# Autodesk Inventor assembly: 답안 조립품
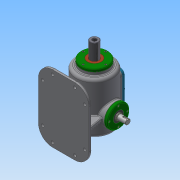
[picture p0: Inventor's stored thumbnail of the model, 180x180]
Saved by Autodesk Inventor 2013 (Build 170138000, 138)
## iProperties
Created: 2019-10
Part Number: 답안 조립품
Document SubType Name: Assembly
Designer: Administrator
Author: Administrator
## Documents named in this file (17)
- C:\Users\Administrator\Desktop\새 폴더\답안 조립품.iam
- C:\Users\Administrator\Desktop\새 폴더\본체.ipt
- C:\Users\Administrator\Desktop\새 폴더\개스킷 A.ipt
- C:\Users\Administrator\Desktop\새 폴더\개스킷 B.ipt
- C:\Users\Administrator\Desktop\새 폴더\고정플레이트.ipt
- C:\Users\Administrator\Desktop\새 폴더\베어링 6205.ipt
- 베어링 6205.ipt
- C:\Users\Administrator\Desktop\새 폴더\볼트 M4x0.7.ipt
- C:\Users\Administrator\Desktop\새 폴더\부시.ipt
- C:\Users\Administrator\Desktop\새 폴더\상부커버.ipt
- C:\Users\Administrator\Desktop\새 폴더\슬라이드 커버.ipt
- C:\Users\Administrator\Desktop\새 폴더\슬라이드.ipt
- C:\Users\Administrator\Desktop\새 폴더\오일 실 25 38 8.ipt
- C:\Users\Administrator\Desktop\새 폴더\육각머리볼트 M4.ipt
- C:\Users\Administrator\Desktop\새 폴더\축 커버.ipt
- C:\Users\Administrator\Desktop\새 폴더\편심축.ipt
- C:\Users\Administrator\Desktop\새 폴더\가변 스프링.ipt
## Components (17 placed, 5 different names)
1. 개스킷 A:1
2. 개스킷 B:1
3. 고정플레이트:1
4. 개스킷 B:2
5. M4x0.7:5
6. M4x0.7:6
7. M4x0.7:7
8. M4x0.7:8
9. 가변 스프링:1
10. M4x0.7:1
11. M4x0.7:2
12. M4x0.7:3
13. M4x0.7:4
14. M4x0.7:9
15. M4x0.7:10
16. M4x0.7:11
17. M4x0.7:12
